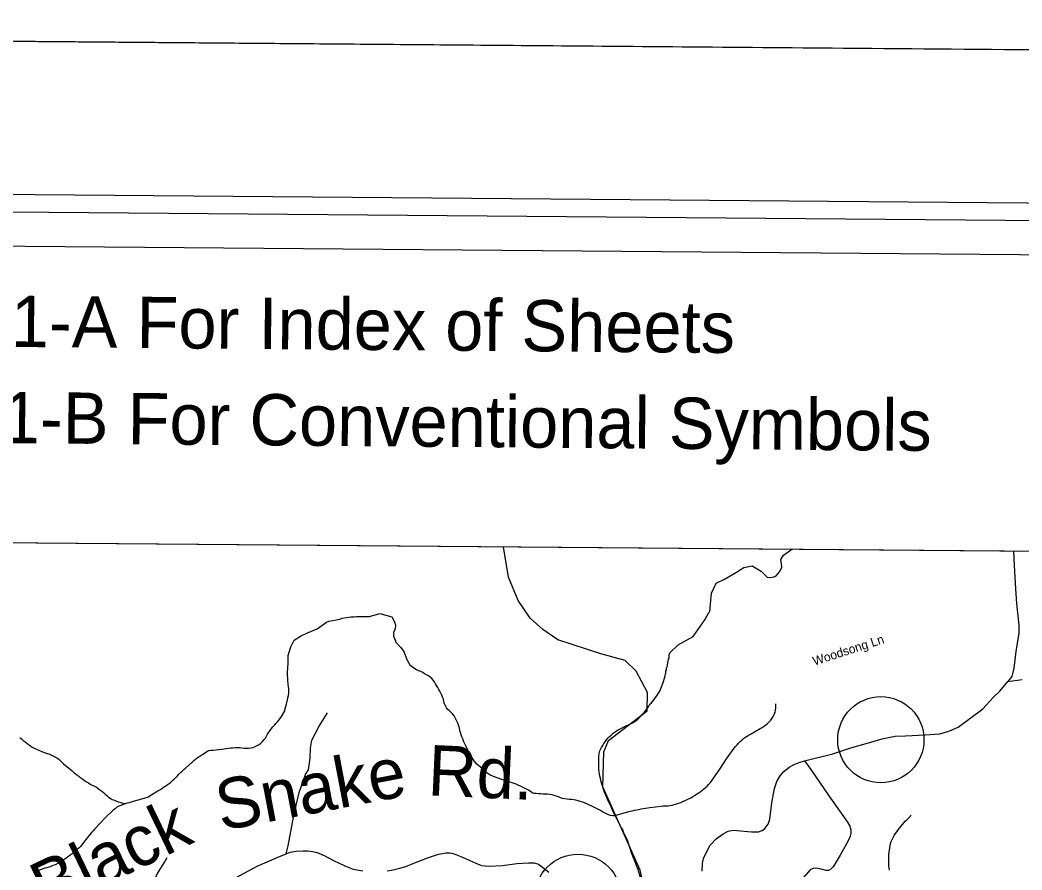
# Model space of a CAD drawing. Extents: x 1379453 to 1387082, y 594364 to 596664.
# Drawn here: x 1380212.5 to 1380505.6, y 596343.6 to 596592.1 of the extents above; entities that cross this region are included whole.
import ezdxf

# ---------------------------------------------------------------- set-up
doc = ezdxf.new("R2010")
doc.units = 0
for name, color, linetype in [('Old_Level_1', 7, 'Continuous'), ('Old_Level_10', 7, 'Continuous'), ('Old_Level_11', 7, 'Continuous'), ('Old_Level_32', 7, 'Continuous'), ('Old_Level_35', 7, 'Continuous'), ('Old_Level_59', 7, 'Continuous'), ('Old_Level_62', 7, 'Continuous'), ('Sheet Clip Boundary CELL', 7, 'Continuous'), ('Sheet Cutting Line CELL', 7, 'Continuous'), ('Sheet Plot Border Inside CELL', 7, 'Continuous'), ('Sheet Plot Border Outside CELL', 7, 'Continuous'), ('Sheet Title CELL', 7, 'Continuous')]:
    doc.layers.add(name, color=color, linetype=linetype)

msp = doc.modelspace()

# ---------------------------------------------------------------- linework, layer by layer
at = {"layer": 'Old_Level_1'}
msp.add_line((1379993.85, 596441.11), (1380745.81, 596434.81), dxfattribs=at)
at = {"layer": 'Old_Level_32'}
for points in [[(1380503.06, 596436.84), (1380503.26, 596432.57), (1380503.67, 596425.77), (1380503.99, 596421.49), (1380504.67, 596415.12), (1380504.65, 596412.81), (1380503.8, 596407.43), (1380503.13, 596402.62), (1380502.54, 596400.19), (1380501.4, 596398.68)], [(1380441.94, 596375.52), (1380450.22, 596377.51), (1380455.83, 596379.44), (1380459.97, 596380.58), (1380464.65, 596381.91), (1380468.47, 596382.69), (1380471.5, 596382.82), (1380477.26, 596383.12), (1380481.5, 596383.39), (1380484.18, 596384.13), (1380486.91, 596385.33), (1380494.08, 596390.67), (1380497.16, 596393.98), (1380499.05, 596395.84), (1380501.4, 596398.68)], [(1380501.4, 596398.68), (1380505.62, 596399.24)], [(1380412.05, 596343.21), (1380412.12, 596345.54), (1380412.5, 596347.21), (1380414.31, 596350.88), (1380416.05, 596352.67), (1380418.16, 596354.17), (1380419.58, 596354.97), (1380421.1, 596355.26), (1380426.42, 596354.69), (1380428.51, 596354.71), (1380429.57, 596355.09), (1380430.31, 596355.69), (1380431.26, 596356.96), (1380431.82, 596358.46), (1380432.36, 596363.24), (1380433.18, 596367.45), (1380433.88, 596369.47), (1380434.83, 596371.14), (1380435.89, 596372.35), (1380437.42, 596373.66), (1380438.94, 596374.41), (1380440.39, 596374.98), (1380441.94, 596375.52)], [(1380441.94, 596375.52), (1380443.8, 596372.99), (1380448.86, 596365.59), (1380454.55, 596357.52), (1380455.22, 596356.35), (1380455.53, 596355.28), (1380455.46, 596354.37), (1380455.19, 596353.05), (1380454.18, 596351.23), (1380452.38, 596347.94), (1380450.36, 596344.46), (1380449.62, 596343.81), (1380448.94, 596343.46), (1380448.31, 596343.41), (1380446.8, 596343.78), (1380445.28, 596344.1), (1380444.34, 596344), (1380443.55, 596343.65), (1380441.68, 596341.42)], [(1380275.52, 596341.25), (1380281.78, 596344.7), (1380287.71, 596347.24), (1380290.27, 596348.25), (1380291.49, 596348.74), (1380293.22, 596349.03), (1380295.32, 596349.21), (1380296.62, 596349.2), (1380297.98, 596348.99), (1380299.34, 596348.67), (1380301.47, 596347.79), (1380304.13, 596346.39), (1380307.47, 596344.79), (1380309.92, 596343.86), (1380312.69, 596343.33)], [(1380319.86, 596343.37), (1380321.64, 596343.66), (1380323.52, 596344.15), (1380325.36, 596344.59), (1380328.14, 596345.79), (1380331.61, 596347.13), (1380334.86, 596348.22), (1380337.11, 596348.56), (1380338.06, 596348.55), (1380338.79, 596348.54), (1380339.94, 596348.13), (1380341.87, 596347.35), (1380344, 596346.32), (1380345.78, 596345.54), (1380347.44, 596344.92), (1380349.64, 596344.69), (1380353.62, 596344.86), (1380357.76, 596345.49), (1380361.21, 596345.71), (1380362.83, 596345.65), (1380364.08, 596345.23), (1380365.33, 596344.41), (1380367.1, 596342.97)]]:
    msp.add_lwpolyline(points, dxfattribs=at)
for centre in [(1380464.28, 596381.66), (1380375.67, 596335.59)]:
    msp.add_circle(centre, 12.61, dxfattribs=at)
at = {"layer": 'Old_Level_35'}
for points in [[(1380290.27, 596348.25), (1380290.88, 596350.67), (1380292.41, 596358.98), (1380294.15, 596366.28), (1380295.97, 596371.54), (1380296.82, 596372.86), (1380297.37, 596376.3), (1380297.4, 596379.15), (1380297.83, 596381.58), (1380299.96, 596385.62), (1380302.4, 596389.56)], [(1380251.23, 596339.32), (1380252.72, 596342.56), (1380254.63, 596345.69), (1380255.48, 596347.21)]]:
    msp.add_lwpolyline(points, dxfattribs=at)
at = {"layer": 'Old_Level_59'}
for points in [[(1380392.66, 596401.71), (1380389.5, 596404.8), (1380382.38, 596406.74), (1380369.8, 596410.83), (1380365.37, 596413.93), (1380361.7, 596417.23), (1380358.15, 596422.4), (1380355.37, 596429.18), (1380353.88, 596438.09)], [(1380489.17, 596236.91), (1380485.22, 596238.73), (1380469.6, 596240.49), (1380463.7, 596244.08), (1380457.52, 596250.16), (1380451.3, 596252.7), (1380437.31, 596254.42), (1380434.37, 596256.6), (1380430.33, 596266.3), (1380423.87, 596273.18), (1380412.42, 596281.52), (1380403.14, 596305.55), (1380399.48, 596318), (1380393.89, 596343.51), (1380382.94, 596367.85), (1380383.23, 596378.09), (1380384.65, 596381.46), (1380395.92, 596390.07), (1380396.05, 596395.45), (1380392.66, 596401.71)]]:
    msp.add_lwpolyline(points, dxfattribs=at)
at = {"layer": 'Old_Level_62'}
for points in [[(1380401.35, 596401.21), (1380401.42, 596401.69), (1380401.59, 596402.01), (1380401.61, 596402.64), (1380401.77, 596402.96), (1380402.16, 596405.19), (1380402.33, 596405.5), (1380402.36, 596406.46), (1380402.54, 596407.09), (1380405, 596409.42), (1380409.4, 596411.84), (1380412.75, 596416.7), (1380413.93, 596418.9), (1380414.26, 596419.21), (1380414.71, 596424.56), (1380416.14, 596427.48), (1380418.57, 596428.61), (1380422.02, 596430.62), (1380424.2, 596432), (1380426.62, 596432.49), (1380429.29, 596430.94), (1380431.04, 596429.25), (1380432, 596429.14), (1380432.96, 596429.27), (1380433.61, 596429.57), (1380434.61, 596430.74), (1380435.28, 596432), (1380435.3, 596432.32), (1380435.05, 596434.33), (1380435.82, 596435.6), (1380437.88, 596437.11), (1380438.43, 596437.38)], [(1380290.93, 596404.43), (1380290.9, 596406.34), (1380291.69, 596408.87), (1380292.63, 596410.77), (1380294.51, 596411.98), (1380296.57, 596412.97), (1380299.37, 596414.08), (1380302.15, 596416.07), (1380302.8, 596416.37), (1380306.01, 596416.91), (1380306.67, 596417.21), (1380309.23, 596417.61), (1380310.19, 596417.58), (1380310.84, 596417.72), (1380314.68, 596417.69), (1380317.67, 596418.54), (1380321.23, 596417.57), (1380321.85, 596416.54), (1380322.3, 596415.23), (1380322.19, 596414.1), (1380321.67, 596412.98), (1380321.72, 596411.93), (1380322.33, 596410.62), (1380322.3, 596410.26), (1380323.85, 596408.61), (1380324.85, 596407.23), (1380325.51, 596405.28), (1380326.54, 596403.39)], [(1380243.15, 596362.96), (1380243.76, 596363.24), (1380244.39, 596363.32), (1380246.29, 596363.85), (1380248.77, 596364.56), (1380249.99, 596364.98), (1380250.56, 596365.31), (1380252.79, 596366.7), (1380253.34, 596367.05), (1380253.9, 596367.4), (1380254.45, 596367.76), (1380255, 596368.12), (1380255.54, 596368.49), (1380256.07, 596368.87), (1380256.58, 596369.28), (1380257.08, 596369.71), (1380257.57, 596370.15), (1380258.04, 596370.61), (1380258.5, 596371.08), (1380258.94, 596371.57), (1380259.39, 596372.05), (1380259.84, 596372.52), (1380260.34, 596372.95), (1380260.87, 596373.34), (1380262.82, 596375.09), (1380263.27, 596375.56), (1380263.77, 596375.98), (1380264.3, 596376.37), (1380264.85, 596376.74), (1380265.39, 596377.1), (1380265.95, 596377.45), (1380267.6, 596378.47), (1380268.24, 596378.57), (1380268.91, 596378.62), (1380271.48, 596378.91), (1380272.13, 596379.04), (1380272.77, 596379.14), (1380273.43, 596379.22), (1380274.08, 596379.29), (1380274.73, 596379.34), (1380275.39, 596379.37), (1380276.05, 596379.38), (1380276.7, 596379.35), (1380277.36, 596379.29), (1380278.02, 596379.23), (1380278.67, 596379.19), (1380279.32, 596379.18), (1380279.98, 596379.25), (1380280.61, 596379.44), (1380281.22, 596379.69), (1380281.82, 596379.96), (1380282.39, 596380.29), (1380282.91, 596380.68), (1380283.38, 596381.14), (1380283.82, 596381.64), (1380284.22, 596382.16), (1380284.57, 596382.72), (1380284.89, 596383.29), (1380285.23, 596383.86), (1380285.6, 596384.4), (1380286, 596384.91), (1380286.44, 596385.41), (1380286.88, 596385.9), (1380287.32, 596386.39), (1380287.75, 596386.88), (1380288.18, 596387.38), (1380288.57, 596387.9), (1380288.9, 596388.46), (1380289.88, 596390.12), (1380290.06, 596390.75), (1380290.23, 596391.39), (1380290.39, 596392.03), (1380290.69, 596393.31), (1380290.84, 596393.96), (1380290.97, 596394.6), (1380291.07, 596395.25), (1380291.13, 596395.9), (1380291.11, 596396.55), (1380291.04, 596397.21), (1380290.94, 596397.86), (1380290.78, 596399.14), (1380290.71, 596401.07), (1380290.74, 596401.72), (1380290.78, 596402.38), (1380290.93, 596404.43)], [(1380331.9, 596400.34), (1380331.36, 596400.67), (1380330.81, 596400.98), (1380330.25, 596401.29), (1380329.68, 596401.59), (1380329.09, 596401.86), (1380328.48, 596402.07), (1380327.93, 596402.41), (1380326.54, 596403.39)], [(1380396.38, 596391.46), (1380396.67, 596392.02), (1380397.16, 596392.45), (1380397.58, 596392.95), (1380397.98, 596393.46), (1380398.35, 596393.97), (1380398.72, 596394.5), (1380399.06, 596395.02), (1380399.39, 596395.55), (1380399.69, 596396.09), (1380399.94, 596396.67), (1380400.58, 596398.37), (1380401.08, 596399.98), (1380401.35, 596401.21)], [(1380386.54, 596359.44), (1380385.88, 596359.45), (1380385.23, 596359.49), (1380384.61, 596359.71), (1380384.03, 596360.01), (1380383.45, 596360.31), (1380382.86, 596360.62), (1380382.29, 596360.93), (1380381.7, 596361.23), (1380381.12, 596361.54), (1380380.54, 596361.84), (1380379.96, 596362.14), (1380377.58, 596363.19), (1380375.72, 596363.79), (1380375.09, 596363.99), (1380374.45, 596364.1), (1380373.79, 596364.17), (1380373.14, 596364.22), (1380372.48, 596364.28), (1380371.83, 596364.36), (1380371.19, 596364.49), (1380370.56, 596364.69), (1380369.95, 596364.93), (1380369.34, 596365.18), (1380368.71, 596365.39), (1380368.08, 596365.54), (1380367.43, 596365.63), (1380366.78, 596365.7), (1380366.12, 596365.75), (1380365.46, 596365.79), (1380364.8, 596365.83), (1380364.14, 596365.87), (1380363.49, 596365.92), (1380362.84, 596365.99), (1380362.24, 596366.16), (1380361.73, 596366.59), (1380361.16, 596366.9), (1380360.58, 596367.21), (1380360, 596367.52), (1380359.41, 596367.82), (1380358.82, 596368.11), (1380358.22, 596368.39), (1380357.63, 596368.64), (1380357.01, 596368.87), (1380356.38, 596369.06), (1380355.75, 596369.24), (1380355.11, 596369.42), (1380354.48, 596369.6), (1380352.04, 596370.49), (1380351.42, 596370.72), (1380350.8, 596370.97), (1380350.21, 596371.24), (1380349.63, 596371.55), (1380349.1, 596371.92), (1380348.6, 596372.35), (1380346.61, 596374.09), (1380346.13, 596374.54), (1380345.68, 596375.01), (1380345.28, 596375.53), (1380344.94, 596376.08), (1380343.59, 596378.31), (1380343.31, 596378.9), (1380343.03, 596379.5), (1380342.76, 596380.09), (1380342.49, 596380.69), (1380342.22, 596381.29), (1380341.95, 596381.9), (1380341.7, 596382.5), (1380341.47, 596383.12), (1380341.27, 596383.74), (1380341.11, 596384.38), (1380340.97, 596385.02), (1380340.82, 596385.66), (1380340.61, 596386.28), (1380340.35, 596386.88), (1380340.06, 596387.47), (1380339.76, 596388.06), (1380339.45, 596388.64), (1380339.07, 596389.17), (1380338.61, 596389.64), (1380338.11, 596390.09), (1380337.62, 596390.54), (1380337.2, 596391.03), (1380336.88, 596391.58), (1380336.65, 596392.2), (1380336.48, 596392.84), (1380336.3, 596393.48), (1380336.08, 596394.09), (1380335.81, 596394.67), (1380335.54, 596395.25), (1380335.25, 596395.82), (1380334.95, 596396.38), (1380334.64, 596396.94), (1380334.33, 596397.5), (1380334.01, 596398.04), (1380333.69, 596398.58), (1380333.35, 596399.11), (1380332.92, 596399.58), (1380332.43, 596399.98), (1380331.9, 596400.34)], [(1380386.54, 596359.44), (1380387.16, 596359.66), (1380390.3, 596360.56), (1380390.93, 596360.74), (1380391.57, 596360.89), (1380392.21, 596361.04), (1380392.85, 596361.18), (1380393.5, 596361.31), (1380394.14, 596361.42), (1380396.72, 596361.81), (1380399.96, 596362.28), (1380400.61, 596362.35), (1380401.27, 596362.35), (1380401.93, 596362.34), (1380402.58, 596362.39), (1380403.22, 596362.53), (1380403.85, 596362.7), (1380404.48, 596362.9), (1380405.11, 596363.12), (1380405.72, 596363.35), (1380406.33, 596363.6), (1380408.64, 596364.65), (1380409.2, 596364.99), (1380409.75, 596365.34), (1380410.3, 596365.71), (1380410.86, 596366.07), (1380411.39, 596366.45), (1380411.93, 596366.84), (1380412.44, 596367.24), (1380412.93, 596367.67), (1380413.42, 596368.13), (1380413.88, 596368.59), (1380414.33, 596369.07), (1380414.76, 596369.57), (1380415.15, 596370.09), (1380417.39, 596373.33), (1380418.06, 596374.45), (1380419.1, 596376.11), (1380421.03, 596378.76), (1380421.8, 596379.66), (1380422.23, 596380.15), (1380422.67, 596380.64), (1380423.11, 596381.13), (1380423.59, 596381.58), (1380424.09, 596382), (1380424.63, 596382.37), (1380425.18, 596382.73), (1380425.74, 596383.08), (1380426.31, 596383.4), (1380427.31, 596383.95), (1380429.01, 596384.94), (1380429.58, 596385.27), (1380430.14, 596385.62), (1380430.67, 596386), (1380431.16, 596386.43), (1380431.61, 596386.92), (1380432.04, 596387.42), (1380432.44, 596387.93), (1380432.79, 596388.49), (1380433.1, 596389.07), (1380433.35, 596389.68), (1380433.5, 596390.31), (1380433.57, 596390.97), (1380433.59, 596392.21)], [(1380386.54, 596359.44), (1380386.27, 596360.04), (1380385.99, 596360.63), (1380385.71, 596361.23), (1380385.44, 596361.83), (1380385.17, 596362.42), (1380384.89, 596363.02), (1380384.62, 596363.61), (1380384.34, 596364.21), (1380384.08, 596364.81), (1380383.81, 596365.41), (1380383.54, 596366.01), (1380383.29, 596366.62), (1380382.52, 596369.1), (1380382.37, 596369.74), (1380382.23, 596370.39), (1380382.1, 596371.03), (1380381.99, 596371.68), (1380381.88, 596372.32), (1380381.8, 596372.97), (1380381.77, 596373.63), (1380381.76, 596374.29), (1380381.77, 596374.94), (1380381.77, 596375.6), (1380381.79, 596376.26), (1380381.82, 596376.92), (1380381.88, 596377.57), (1380382.01, 596378.22), (1380382.26, 596378.83), (1380382.57, 596379.4), (1380382.9, 596379.97), (1380383.25, 596380.53), (1380383.62, 596381.07), (1380384.01, 596381.6), (1380384.42, 596382.11), (1380384.87, 596382.59), (1380385.35, 596383.04), (1380385.85, 596383.47), (1380386.36, 596383.88), (1380386.91, 596384.24), (1380387.47, 596384.59), (1380389.22, 596385.47), (1380390.99, 596386.33), (1380391.58, 596386.61), (1380392.15, 596386.94), (1380392.69, 596387.31), (1380393.21, 596387.72), (1380393.69, 596388.16), (1380394.15, 596388.63), (1380394.58, 596389.13), (1380395, 596389.63), (1380395.4, 596390.15), (1380396.38, 596391.46)], [(1380212.41, 596382.32), (1380212.91, 596381.89), (1380213.41, 596381.46), (1380213.92, 596381.05), (1380214.44, 596380.64), (1380214.96, 596380.25), (1380215.49, 596379.88), (1380216.05, 596379.53), (1380216.63, 596379.23), (1380217.23, 596378.95), (1380219.04, 596378.15), (1380219.64, 596377.89), (1380220.25, 596377.65), (1380220.89, 596377.52), (1380221.49, 596377.27), (1380222.09, 596376.99), (1380222.68, 596376.7), (1380223.25, 596376.39), (1380223.78, 596376), (1380224.26, 596375.54), (1380224.71, 596375.08), (1380225.19, 596374.62), (1380227.7, 596372.53), (1380228.21, 596372.12), (1380228.73, 596371.72), (1380229.25, 596371.32), (1380229.77, 596370.92), (1380230.29, 596370.52), (1380230.82, 596370.13), (1380231.36, 596369.75), (1380231.9, 596369.37), (1380232.44, 596369.02), (1380233.01, 596368.69), (1380233.6, 596368.4), (1380234.2, 596368.11), (1380234.78, 596367.8), (1380235.33, 596367.45), (1380235.85, 596367.05), (1380236.35, 596366.64), (1380236.85, 596366.2), (1380237.34, 596365.76), (1380237.84, 596365.33), (1380238.34, 596364.91), (1380238.87, 596364.53), (1380239.45, 596364.22), (1380240.06, 596363.96), (1380240.68, 596363.74), (1380241.3, 596363.53), (1380241.93, 596363.34), (1380243.15, 596362.96)], [(1380243.15, 596362.96), (1380241.93, 596362.47), (1380241.33, 596362.21), (1380240.76, 596361.9), (1380240.24, 596361.49), (1380239.75, 596361.05), (1380237.35, 596358.8), (1380236.06, 596357.42), (1380234.26, 596355.5), (1380233.83, 596355.01), (1380233.4, 596354.51), (1380231.72, 596352.49), (1380230.54, 596350.97), (1380230.14, 596350.45), (1380229.68, 596349.99), (1380229.2, 596349.55), (1380228.7, 596349.12), (1380228.18, 596348.7), (1380227.67, 596348.29), (1380227.15, 596347.9), (1380226.62, 596347.5), (1380226.09, 596347.12), (1380225.54, 596346.74), (1380224.99, 596346.38), (1380224.44, 596346.04), (1380223.87, 596345.71), (1380223.3, 596345.39), (1380222.7, 596345.11), (1380222.1, 596344.84), (1380221.49, 596344.59), (1380220.88, 596344.36), (1380220.24, 596344.24), (1380219.6, 596344.08), (1380218.98, 596343.86), (1380218.38, 596343.6), (1380217.78, 596343.33)], [(1380386.54, 596359.44), (1380387.1, 596358.25), (1380388.33, 596355.94), (1380388.65, 596355.37), (1380388.94, 596354.78), (1380389.21, 596354.18), (1380389.49, 596353.58), (1380389.76, 596352.98), (1380390.02, 596352.38), (1380390.41, 596351.16), (1380390.8, 596349.93), (1380391.24, 596348.7), (1380392.17, 596346.28), (1380392.91, 596344.46), (1380393.14, 596343.84), (1380394.21, 596340.08)], [(1380466.83, 596343.52), (1380466.67, 596344.15), (1380466.59, 596344.8), (1380466.57, 596345.45), (1380466.57, 596346.11), (1380466.59, 596347.43), (1380466.61, 596348.09), (1380466.66, 596348.74), (1380467.05, 596351.33), (1380467.25, 596351.94), (1380467.54, 596352.53), (1380467.86, 596353.11), (1380468.2, 596353.67), (1380468.56, 596354.22), (1380468.94, 596354.76), (1380469.32, 596355.3), (1380469.73, 596355.81), (1380470.13, 596356.33), (1380470.56, 596356.84), (1380470.98, 596357.33), (1380471.43, 596357.81), (1380471.9, 596358.27), (1380472.4, 596358.7), (1380473.13, 596359.63)]]:
    msp.add_lwpolyline(points, dxfattribs=at)
at = {"layer": 'Sheet Clip Boundary CELL'}
msp.add_lwpolyline([(1379993.85, 596441.11), (1380745.81, 596434.81), (1380742.6, 596052.18), (1380696.17, 596052.63), (1380694.49, 595820.94), (1379988.71, 595826.86)], close=True, dxfattribs=at)
at = {"layer": 'Sheet Cutting Line CELL'}
msp.add_line((1379471.02, 596592.12), (1382838.9, 596563.91), dxfattribs=at)
at = {"layer": 'Sheet Plot Border Inside CELL'}
msp.add_lwpolyline([(1379478.96, 594436.88), (1382811.85, 594408.96), (1382829.53, 596519.08), (1379496.64, 596547.01)], close=True, dxfattribs=at)
at = {"layer": 'Sheet Plot Border Outside CELL'}
msp.add_lwpolyline([(1382838.9, 596563.91), (1379471.02, 596592.12), (1379452.59, 594392.22), (1382820.47, 594364.01)], close=True, dxfattribs=at)
at = {"layer": 'Sheet Title CELL'}
for points in [[(1382784.51, 596514.36), (1379824.56, 596539.18)], [(1382774.4, 596504.45), (1379934.53, 596528.24)]]:
    msp.add_lwpolyline(points, dxfattribs=at)

# ---------------------------------------------------------------- texts
at = {"layer": 'Old_Level_10'}
msp.add_text('Woodsong Ln', height=2.6247, rotation=17.9093, dxfattribs=at).set_placement((1380444.85, 596403.31))
at = {"layer": 'Old_Level_11'}
for s, rotation, p in [('Rd.', 357.4548, (1380331.54, 596365.43)), ('Snake', 10.7743, (1380271.26, 596354.96)), ('Black', 25.6884, (1380220.3, 596330.85))]:
    msp.add_text(s, height=14.764, rotation=rotation, dxfattribs=at).set_placement(p)
at = {"layer": 'Sheet Title CELL'}
for s, p in [('See Sheet 1-A For Index of Sheets', (1380110.45, 596497.36)), ('See Sheet 1-B For Conventional Symbols', (1380107.83, 596469.23))]:
    msp.add_text(s, height=15, rotation=359.52, dxfattribs=at).set_placement(p)

doc.saveas('drawing.dxf')
